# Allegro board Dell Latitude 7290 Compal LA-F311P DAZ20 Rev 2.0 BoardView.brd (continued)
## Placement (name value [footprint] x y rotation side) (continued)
PR1258  0_0402_5%  [R_0402]  45.6 52.84 0 bottom
PR1259  100K_0402_5%  [R_0402]  41.54 52.84 0 bottom
PR1260  0_0402_5%  [R_0402]  40.71 51.13 0 top
PR1261  0_0402_5%  [R_0402]  42.95 51.46 270 top
PR1262  100K_0402_1%  [R_0402]  46.33 108.98 180 top
PRP1  100_0804_8P4R_5%  [RP_0804_8P4R]  167.81 61.67 45 top
PT1  PAD~D  [TPC12]  32.51 58.58 0 top
PU1  MC74VHC1G08DFT2G SC70 5P AND  [TC7SH08FU_SSOP5]  56.85 121.18 270 bottom
PU2  AP2204R-3.3TRG1 SOT-89 3P LDO  [AP2204R-5P0TRG1_SOT89-3]  68.22 121.02 270 bottom
PU100  -  [SY8288BRAC_QFN20_3X3]  155.36 73.9 90 bottom
PU102  SYV828CRAC QFN 20P PWM  [SY8288CRAC_QFN20_3X3]  185.84 54.09 90 bottom
PU200  -  [SY8210AQVC_QFN19_4X3]  69.06 72.01 180 bottom
PU301  SY8286RAC_QFN20_3X3  [SY8288RAC_QFN20_3X3]  157.04 86.35 270 top
PU401  TPS62134CRGT_QFN16_3X3  [SY8057QDC_QFN16_3X3]  140.08 129.05 0 bottom
PU402  TPS62134DRGT_QFN16_3X3  [SY8057QDC_QFN16_3X3]  155.95 127.53 0 bottom
PU501  -  [RT8097ALGE_SOT23-6]  174.39 65.56 225 bottom
PU503  AP7361C-FGE-7-01 U-DFN3030 8P LDO  [AP7361C-FGE-7_U-DFN3030-8_3X3]  148.3 60.61 270 top
PU602  ISL95857AHRTZ-T TQFN 40P PWM  [ISL62883CHRTZ-T_TQFN40_5X5-S]  46.33 91.69 0 top
PU610  FDMF3035_PQFN31_5X5  [NCP302045MNTWG_PQFN33_5X5]  59.64 106.09 180 bottom
PU612  FDMF3035_PQFN31_5X5  [NCP302045MNTWG_PQFN33_5X5]  59.69 86.7 180 bottom
PU613  FDMF3035_PQFN31_5X5  [NCP302045MNTWG_PQFN33_5X5]  56.49 95.82 90 bottom
PU614  S IC ISL95808HRZ-TS2778 DFN MOSFET DRIVE  [ISL95808HRZ-TS2378_DFN8_2X2-S]  60.01 113.56 90 bottom
PU901  S IC ISL9538HRTZ-REV.C-T TQFN32P CHARGER  [ISL88738HRTZ-T_TQFN32_4X4]  58.57 55.64 180 top
PU903  MC74VHC1G08DFT2G SC70 5P AND  [TC7SH08FU_SSOP5]  46.25 55.4 270 bottom
PU1200  MC74VHC1G08DFT2G SC70 5P AND  [TC7SH08FU_SSOP5]  37.51 62.6 270 bottom
PU1201  -  [LM393DGKR_VSSOP8]  41.44 56.04 180 bottom
QC2  -  [DMN65D8LDW-7_SOT363-6]  150.96 109.75 270 bottom
QC6  -  [L2N7002WT1G_SC-70-3]  142.53 75.88 90 top
QC7  -  [LP2301ALT1G_SOT23-3]  149.27 83.49 270 bottom
QE2  -  [DMN65D8LDW-7_SOT363-6]  238.86 83.83 180 bottom
QE3  LMBT3904WT1G SC70-3  [MMBT3904WT1G_SC70-3]  117.93 101.69 90 top
QE4  LMBT3904WT1G SC70-3  [MMBT3904WT1G_SC70-3]  265.9 101.86 90 top
QE5  LMBT3904WT1G SC70-3  [MMBT3904WT1G_SC70-3]  235.99 79.39 90 top
QE6  LMBT3904WT1G SC70-3  [MMBT3904WT1G_SC70-3]  66.53 83.82 90 bottom
QE7  LMBT3904WT1G SC70-3  [MMBT3904WT1G_SC70-3]  149.57 59.52 0 bottom
QE11  -  [L2N7002WT1G_SC-70-3]  258.92 102.69 90 top
QE12  -  [L2N7002WT1G_SC-70-3]  245.9 102.81 0 top
QE15  -  [LP2301ALT1G_SOT23-3]  241.33 97.04 270 top
QE17  -  [L2N7002WT1G_SC-70-3]  233.13 97.11 0 top
QL1  -  [DMN65D8LDW-7_SOT363-6]  257.79 131.2 180 bottom
QL2  -  [DMN65D8LDW-7_SOT363-6]  260.64 131.2 180 bottom
QR1  -  [L2N7002WT1G_SC-70-3]  279.87 58.56 90 top
QT1  -  [DMN66D0LDW-7_SOT363-6]  39.96 80.26 90 top
QV1  -  [AO6405_TSOP6]  46.25 125.07 180 top
QV2  -  [L2N7002WT1G_SC-70-3]  40.47 123.13 0 top
QV3  -  [DMN65D8LDW-7_SOT363-6]  17.57 88.22 0 top
QV4  -  [L2N7002WT1G_SC-70-3]  22.19 75.19 0 top
QV5  -  [L2N7002WT1G_SC-70-3]  12.66 95.26 180 top
QV7  -  [L2N7002WT1G_SC-70-3]  48.6 122.17 0 top
QV8  -  [LP2301ALT1G_SOT23-3]  49.17 126.15 180 top
QZ1  -  [LP2301ALT1G_SOT23-3]  57.16 125.79 180 top
QZ2  -  [DMN65D8LDW-7_SOT363-6]  270.98 84.54 270 top
QZ3  DDTA144VCA-7-F_SOT23-3  [DDTA114EUA-7-F_SOT323-3]  285.84 11.35 0 bottom
QZ4  -  [L2N7002WT1G_SC-70-3]  241.5 120.81 270 bottom
QZ7  -  [DMN65D8LDW-7_SOT363-6]  268.56 82.23 90 top
QZ15  S TR BSS138W 1N SOT-323-3  [L2N7002WT1G_SC-70-3]  248.28 121.16 0 bottom
RA3  0_0603_5%  [R0603_0OHM]  263.29 55.76 0 top
RA5  2.2K_0402_5%  [R_0402]  250.9 61.86 0 top
RA6  2.2K_0402_5%  [R_0402]  250.9 60.97 0 top
RA7  16.2_0402_1%  [R_0402]  258.34 55.01 270 top
RA8  16.2_0402_1%  [R_0402]  259.23 55.01 270 top
RA9  33_0402_5%  [R_0402]  256.56 66.38 270 top
RA12  1K_0402_5%  [R_0402]  252.3 66.46 0 top
RA13  1K_0402_5%  [R_0402]  251.43 66.46 180 top
RA14  22_0402_5%  [R_0402]  258.6 66.38 270 top
RA17  33_0402_5%  [R_0402]  257.71 65.47 90 top
RA18  10K_0402_5%  [R_0402]  262.99 67.45 180 top
RA35  0_0402_5%  [R0402_0OHM]  251.37 53.03 180 top
RA36  0_0402_5%  [R0402_0OHM]  251.37 52.14 180 top
RA37  0_0402_5%  [R0402_0OHM]  250.1 59.95 180 top
RA38  0_0402_5%  [R0402_0OHM]  281.75 46.79 90 top
RA39  0_0402_5%  [R0402_0OHM]  282.45 31.54 225 top
RA44  100K_0402_5%  [R_0402]  254.47 55.01 270 top
RA45  10K_0402_5%  [R_0402]  251.43 65.57 180 top
RA48  0_0402_5%  [R0402_0OHM]  261.77 69.49 270 top
RA50  0_0402_5%  [R_0402]  260.88 69.49 270 top
RA51  10K_0402_5%  [R_0402]  252.3 65.57 0 top
RA52  100K_0402_5%  [R_0402]  259.55 66.38 270 top
RA53  0_0402_5%  [R_0402]  250.1 58.18 180 top
RA54  0_0402_5%  [R0402_0OHM]  250.1 59.07 180 top
RA55  0_0402_5%  [R0402_0OHM]  281.32 36.9 0 top
RA56  0_0402_5%  [R0402_0OHM]  281.32 35.7 0 top
RA57  4.7K_0402_5%  [R_0402]  257.45 55.01 270 top
RA58  4.7K_0402_5%  [R_0402]  256.56 55.01 270 top
RA59  100K_0402_1%  [R_0402]  251.98 69.16 0 top
RA60  200K_0402_1%  [R_0402]  253.76 69.16 0 top
RA61  100K_0402_5%  [R_0402]  252.12 68.22 270 top
RC1  100K_0402_5%  [R_0402]  129.92 106.92 0 top
RC2  24.9_0402_1%  [R_0402]  102.75 109.98 270 top
RC3  100_0402_1%  [R_0402]  125.32 120.53 180 top
RC4  200_0402_1%  [R_0402]  137.17 96.21 0 bottom
RC5  121_0402_1%  [R_0402]  120.74 84.48 270 top
RC6  80.6_0402_1%  [R_0402]  122.01 84.48 270 top
RC7  100_0402_1%  [R_0402]  122.9 84.48 270 top
RC10  1K_0402_1%  [R_0402]  148.99 100.35 270 top
RC11  1K_0402_1%  [R_0402]  148.93 91.75 0 bottom
RC12  1K_0402_5%  [R_0402]  134.52 104.84 90 top
RC14  1K_0402_5%  [R_0402]  135.41 104.84 270 top
RC15  1K_0402_5%  [R_0402]  142.19 105.93 0 bottom
RC16  15_0402_5%  [R_0402]  148.92 90.75 0 bottom
RC17  1K_0402_5%  [R_0402]  142.19 106.7 0 bottom
RC19  499_0402_1%  [R_0402]  142.57 102.37 0 bottom
RC20  499_0402_1%  [R_0402]  142.19 103.26 0 bottom
RC21  8.2K_0402_1%  [R_0402]  144.53 84.72 0 top
RC22  22_0402_5%  [R_0402]  137.5 84.48 270 top
RC23  2.2K_0402_5%  [R_0402]  132.35 105.67 0 top
RC25  4.7K_0402_5%  [R_0402]  142.19 105.04 0 bottom
RC27  8.2K_0402_5%  [R_0402]  136.61 84.48 270 top
RC28  33_0402_5%  [R_0402]  157.28 102.21 180 top
RC29  33_0402_5%  [R_0402]  156.97 93.45 270 top
RC30  1K_0402_5%  [R_0402]  160.49 96.42 270 top
RC31  1K_0402_5%  [R_0402]  160.49 93.6 90 top
RC32  0_0402_5%  [R_0402]  163.74 102.5 180 bottom
RC33  0_0402_5%  [R0402_0OHM]  162.83 100.47 0 bottom
RC34  0_0402_5%  [R0402_0OHM]  162.83 99.39 0 bottom
RC35  0_0402_5%  [R0402_0OHM]  163.74 97.93 180 bottom
RC36  0_0402_5%  [R0402_0OHM]  163.74 95.83 180 bottom
RC37  0_0402_5%  [R0402_0OHM]  163.74 96.72 180 bottom
RC38  0_0402_5%  [R0402_0OHM]  163.66 93.91 90 bottom
RC39  33_0402_5%  [R_0402]  161.38 96.42 270 top
RC40  0_0402_5%  [R0402_0OHM]  163.66 92.07 90 bottom
RC41  0_0402_5%  [R0402_0OHM]  149.95 101.22 90 top
RC42  0_0402_5%  [R_0402]  163.74 101.61 180 bottom
RC43  33_0402_5%  [R_0402]  161.39 97.29 180 top
RC44  113_0402_1%  [R_0402]  130.99 102.58 90 top
RC45  100_0402_1%  [R_0402]  129.96 109.58 0 top
RC46  1M_0402_1%  [R_0402]  114.32 118.12 0 bottom
RC47  10K_0402_5%  [R_0402]  144.75 96.61 180 bottom
RC48  1K_0402_5%  [R_0402]  124.31 82.69 180 top
RC50  10K_0402_5%  [R_0402]  144.76 95.84 180 bottom
RC51  10K_0402_5%  [R_0402]  144.75 98.31 180 bottom
RC52  2.7K_0402_1%  [R_0402]  119.3 104.96 90 top
RC54  10M_0402_5%  [R_0402]  133.87 82.62 0 top
RC56  20K_0402_5%  [R_0402]  130.77 82.26 270 top
RC57  20K_0402_5%  [R_0402]  128.93 80.66 0 top
RC59  10K_0402_5%  [R_0402]  138.82 83.58 0 top
RC60  0_0402_5%  [R_0402]  157.94 118.57 0 bottom
RC62  0_0402_5%  [R0402_0OHM]  157.94 119.45 0 bottom
RC65  100K_0402_5%  [R_0402]  155.33 117.42 0 bottom
RC67  1K_0402_5%  [R_0402]  136.61 79.44 90 top
RC68  10K_0402_5%  [R_0402]  141.62 81.29 0 top
RC69  1M_0402_5%  [R_0402]  127.42 83.58 180 top
RC71  1K_0402_5%  [R_0402]  90.89 120.65 90 bottom
RC72  8.2K_0402_5%  [R_0402]  131.02 84.48 270 top
RC73  10K_0402_5%  [R_0402]  141.57 84.86 270 top
RC74  10K_0402_5%  [R_0402]  143.35 84.56 270 top
RC75  10K_0402_5%  [R_0402]  126.71 81.43 270 top
RC77  1K_0402_5%  [R_0402]  84.78 121.17 0 bottom
RC78  60.4_0402_1%  [R_0402]  90.89 119.78 270 bottom
RC79  49.9_0402_1%  [R_0402]  96.29 119.76 90 bottom
RC80  1K_0402_5%  [R_0402]  95.41 120.66 180 bottom
RC81  51_0402_5%  [R_0402]  99.02 121.09 90 bottom
RC82  100_0402_5%  [R_0402]  99.91 121.09 90 bottom
RC83  1K_0402_5%  [R_0402]  89.11 120.65 90 bottom
RC84  499_0402_1%  [R_0402]  88.23 119.78 270 bottom
RC86  51_0402_5%  [R_0402]  99.83 120.53 0 top
RC87  1K_0402_5%  [R_0402]  98.07 119.76 90 bottom
RC88  49.9_0402_1%  [R_0402]  123.79 84.48 270 top
RC89  49.9_0402_1%  [R_0402]  125.12 84.48 270 top
RC90  49.9_0402_1%  [R_0402]  92.71 109.36 180 top
RC91  49.9_0402_1%  [R_0402]  92.71 108.47 180 top
RC92  33_0402_5%  [R_0402]  119.98 79.87 90 top
RC93  33_0402_5%  [R_0402]  119.09 79.87 90 top
RC94  33_0402_5%  [R_0402]  124.13 77.63 180 top
RC95  33_0402_5%  [R_0402]  122.32 76.78 90 top
RC96  200_0402_1%  [R_0402]  129.31 103.47 0 top
RC109  1K_0402_5%  [R_0402]  84.48 118.87 90 bottom
RC110  10K_0402_1%  [R_0402]  87.21 118.87 90 bottom
RC112  10K_0402_1%  [R_0402]  86.32 118.87 90 bottom
RC113  10K_0402_1%  [R_0402]  87.48 120.66 180 bottom
RC114  49.9_0402_1%  [R_0402]  97.69 110.09 180 top
RC115  1.5K_0402_5%  [R_0402]  89.04 133.17 0 top
RC120  100K_0402_5%  [R_0402]  91.78 118.87 90 bottom
RC121  0_0402_5%  [R_0402]  99.02 127.13 90 bottom
RC122  0_0402_5%  [R_0402]  98.13 127.13 90 bottom
RC123  1K_0402_5%  [R_0402]  90 120.65 90 bottom
RC124  1K_0402_5%  [R_0402]  124.93 81.43 270 top
RC126  1K_0402_5%  [R_0402]  90.26 126.24 90 bottom
RC128  0_0402_5%  [R_0402]  88.48 126.24 90 bottom
RC129  0_0402_5%  [R_0402]  89.37 126.24 90 bottom
RC130  51_0402_5%  [R_0402]  101.62 120.52 90 top
RC131  51_0402_5%  [R_0402]  78.41 121.9 270 bottom
RC132  150_0402_5%  [R_0402]  92.04 127.15 270 bottom
RC133  1.5K_0402_5%  [R_0402]  148.99 101.22 90 top
RC134  51_0402_5%  [R_0402]  79.78 119.78 270 bottom
RC135  100_0402_5%  [R_0402]  82 119.78 270 bottom
RC136  51_0402_5%  [R_0402]  82.46 125.16 0 bottom
RC137  3K_0402_5%  [R_0402]  88.17 133.17 180 top
RC138  51_0402_5%  [R_0402]  102.89 127.98 270 bottom
RC139  51_0402_5%  [R_0402]  86.69 128.03 0 bottom
RC140  100_0402_1%  [R_0402]  110.08 120.53 180 top
RC141  100_0402_1%  [R_0402]  110.95 120.53 0 top
RC143  0_0603_5%  [R0603_0OHM]  118.64 108.72 180 top
RC152  56_0402_1%  [R_0402]  93.57 120.66 180 bottom
RC153  220_0402_5%  [R_0402]  93.56 118.87 90 bottom
RC157  100_0402_1%  [R_0402]  92.67 118.87 90 bottom
RC161  100_0402_1%  [R_0402]  88.47 107.39 0 top
RC163  100_0402_1%  [R_0402]  88.47 108.28 0 top
RC165  100_0402_1%  [R_0402]  117.64 96.89 135 top
RC166  100_0402_1%  [R_0402]  117.75 120.46 90 top
RC167  100_0402_1%  [R_0402]  118.76 97.22 135 top
RC168  100_0402_1%  [R_0402]  116.86 121.37 270 top
RC169  0_0603_5%  [R0603_0OHM]  129.31 126.57 270 bottom
RC170  0_0402_5%  [R0402_0OHM]  124.99 127.95 270 bottom
RC171  0_0402_5%  [R0402_0OHM]  125.88 127.95 270 bottom
RC173  0_0402_5%  [R0402_0OHM]  122.33 127.95 270 bottom
RC175  2.2K_0402_5%  [R_0402]  132.03 109.94 0 top
RC176  2.2K_0402_5%  [R_0402]  148.99 113.31 270 top
RC177  2.2K_0402_5%  [R_0402]  148.99 114.17 90 top
RC178  2.2K_0402_5%  [R_0402]  132.03 109.05 0 top
RC183  8.2K_0402_5%  [R_0402]  140.68 84.86 270 top
RC184  8.2K_0402_5%  [R_0402]  140.1 97.98 90 top
RC186  4.7K_0402_5%  [R_0402]  134.83 84.48 270 top
RC187  4.7K_0402_5%  [R_0402]  123.21 79.36 0 top
RC189  10K_0402_5%  [R_0402]  144.75 97.42 180 bottom
RC190  10K_0402_5%  [R_0402]  138.82 82.69 0 top
RC211  0_0402_5%  [R_0402]  145.05 81.54 0 top
RC212  0_0402_5%  [R0402_0OHM]  148.11 85.62 270 top
RC214  0_0402_5%  [R_0402]  147.9 80.02 270 top
RC215  0_0402_5%  [R_0402]  125.82 80.52 90 top
RC216  0_0603_5%  [R0603_0OHM]  93.37 133.55 180 top
RC217  0_0402_5%  [R_0402]  91.15 126.24 90 bottom
RC218  150_0402_5%  [R_0402]  92.04 125.37 270 bottom
RC219  10K_0402_5%  [R_0402]  91.15 125.37 270 bottom
RC220  100K_0402_1%  [R_0402]  125.8 78.75 0 top
RC221  0_0402_5%  [R0402_0OHM]  230.69 87.77 335 bottom
RC222  1K_0402_5%  [R_0402]  226.85 80.98 225 bottom
RC223  1K_0402_5%  [R_0402]  124.13 78.5 180 top
RC224  1K_0402_5%  [R_0402]  149.83 114.31 180 bottom
RC225  8.2K_0402_5%  [R_0402]  149.64 117.74 180 bottom
RC227  8.2K_0402_5%  [R_0402]  150.51 117.74 0 bottom
RC228  0_0402_5%  [R0402_0OHM]  77.46 121.9 270 bottom
RC229  0_0402_5%  [R0402_0OHM]  80.67 119.78 270 bottom
RC230  0_0402_5%  [R0402_0OHM]  82.89 119.78 270 bottom
RC231  0_0402_5%  [R0402_0OHM]  109.55 97.52 0 top
RC234  0_0402_5%  [R_0402]  139.67 100.85 180 top
RC235  0_0402_5%  [R0402_0OHM]  137.88 99.95 90 top
RC237  10K_0402_5%  [R_0402]  140.1 96.71 90 bottom
RC239  0_0402_5%  [R_0402]  97.24 127.13 90 bottom
RC240  0_0402_5%  [R_0402]  96.35 127.13 90 bottom
RC241  1.5K_0402_5%  [R_0402]  91.35 127.2 180 top
RC243  10K_0402_5%  [R_0402]  137.5 79.44 90 top
RC244  0_0402_5%  [R0402_0OHM]  157.94 120.34 0 bottom
RC267  10K_0402_5%  [R_0402]  138.31 97.61 0 bottom
RC268  10K_0402_5%  [R_0402]  137.25 97.22 90 bottom
RC272  10K_0402_5%  [R_0402]  128.54 117.72 0 bottom
RC278  10K_0402_5%  [R_0402]  141.9 98.94 180 bottom
RC279  10K_0402_5%  [R_0402]  147.22 106.11 90 bottom
RC282  100K_0402_5%  [R_0402]  144.98 85.61 0 top
RC283  10K_0402_5%  [R_0402]  145.64 101.48 180 bottom
RC287  100K_0402_5%  [R_0402]  134.36 102.96 0 top
RC288  10K_0402_5%  [R_0402]  135.91 121.12 90 bottom
RC290  0_0402_5%  [R0402_0OHM]  151.81 114.31 180 bottom
RC291  10K_0402_5%  [R_0402]  147.98 115.95 90 bottom
RC292  10K_0402_5%  [R_0402]  139.08 98.94 0 bottom
RC296  0_0402_5%  [R0402_0OHM]  132.94 82.62 180 top
RC297  0_0402_5%  [R_0402]  104.93 120.52 90 top
RC298  0_0402_5%  [R_0402]  103.78 120.52 90 top
RC299  0_0603_5%  [R0603_0OHM]  140.8 121.23 270 top
RC300  0_0402_5%  [R0402_0OHM]  127.66 122.52 270 bottom
RC301  0_0402_5%  [R0402_0OHM]  149.71 106.56 180 bottom
RC302  0_0402_5%  [R0402_0OHM]  125.82 123.63 270 top
RC303  0_0402_5%  [R0402_0OHM]  124.93 123.63 270 top
RC304  0_0402_5%  [R0402_0OHM]  131.55 100.98 180 top
RC305  0_0402_5%  [R0402_0OHM]  130.64 98.49 90 top
RC306  0_0402_5%  [R0402_0OHM]  135.22 99.38 90 top
RC307  0_0402_5%  [R0402_0OHM]  134.33 99.38 90 top
RC308  0_0402_5%  [R0402_0OHM]  136.42 103.06 90 top
RC309  0_0603_5%  [R0603_0OHM]  136.04 121.99 270 top
RC310  0_0603_5%  [R0603_0OHM]  129.44 123.77 270 top
RC311  10K_0402_5%  [R_0402]  128.93 84.48 270 top
RC313  0_0402_5%  [R_0402]  139.04 101.8 180 bottom
RC316  1K_0402_5%  [R_0402]  160.49 92.73 270 top
RC317  150K_0402_5%  [R_0402]  139.22 97.98 90 top
RC318  2.2K_0402_5%  [R_0402]  148.12 107.96 180 bottom
RC319  2.2K_0402_5%  [R_0402]  149.86 111.06 180 bottom
RC323  10K_0402_5%  [R_0402]  146.89 102.37 0 bottom
RC324  59_0402_1%  [R_0402]  108.29 110.07 270 top
RC325  0_0402_5%  [R0402_0OHM]  157.94 117.68 0 bottom
RC328  0_0402_5%  [R0402_0OHM]  96.59 118.88 0 bottom
RC330  49.9K_0402_1%  [R_0402]  146 100.21 0 bottom
RC331  49.9K_0402_1%  [R_0402]  146 99.32 0 bottom
RC337  0_0402_5%  [R0402_0OHM]  137.88 111.57 90 bottom
RC338  1K_0402_5%  [R_0402]  136.99 111.57 90 bottom
RC344  10K_0402_5%  [R_0402]  141.57 82.17 90 top
RC345  100K_0402_5%  [R_0402]  135.61 108.28 180 bottom
RC346  10K_0402_5%  [R_0402]  136.8 121.12 90 bottom
RC347  499_0402_1%  [R_0402]  142.57 101.48 0 bottom
RC348  499_0402_1%  [R_0402]  142.19 104.15 0 bottom
RC349  100_0402_1%  [R_0402]  137.95 82.7 270 top
RC362  1K_0402_5%  [R_0402]  141.9 97.17 180 bottom
RC363  1K_0402_5%  [R_0402]  141.9 98.05 180 bottom
RC366  15_0402_5%  [R_0402]  148.92 85.9 0 bottom
RC367  15_0402_5%  [R_0402]  148.92 87.68 0 bottom
RC368  15_0402_5%  [R_0402]  148.92 86.79 0 bottom
RC369  15_0402_5%  [R_0402]  148.92 88.57 0 bottom
RC371  10K_0402_5%  [R_0402]  140.12 107.39 180 bottom
RC372  10K_0402_5%  [R_0402]  140.12 108.28 180 bottom
RC373  0_0402_5%  [R0402_0OHM]  146.91 97.42 180 bottom
RC374  0_0402_5%  [R0402_0OHM]  146.91 96.53 180 bottom
RC376  0_0402_5%  [R0402_0OHM]  139.74 84.47 180 top
RC377  0_0402_5%  [R0402_0OHM]  146.91 98.31 180 bottom
RC378  0_0402_5%  [R0402_0OHM]  139.74 81.8 180 top
RC387  10K_0402_5%  [R_0402]  142.45 84.86 270 top
RC400  10K_0402_5%  [R_0402]  136.66 107.39 0 bottom
RC401  10K_0402_5%  [R_0402]  136.66 108.28 0 bottom
RC402  49.9K_0402_1%  [R_0402]  143.27 100.28 0 bottom
RC403  49.9K_0402_1%  [R_0402]  143.27 99.39 0 bottom
RC405  100K_0402_5%  [R_0402]  137.25 101.34 90 bottom
RC407  33_0402_5%  [R_0402]  155.85 97.92 90 top
RC408  33_0402_5%  [R_0402]  156.74 97.92 90 top
RC409  33_0402_5%  [R_0402]  157.63 97.92 90 top
RC410  33_0402_5%  [R_0402]  158.65 97.92 90 top
RC411  10K_0402_5%  [R_0402]  122.82 81.8 0 top
RC412  10K_0402_5%  [R_0402]  146.09 107.96 180 bottom
RC413  10K_0402_5%  [R_0402]  133.63 103.84 0 top
RC414  10K_0402_5%  [R_0402]  135.72 84.48 270 top
RC415  1M_0402_1%  [R_0402]  130.76 118.76 0 bottom
RC417  0_0402_5%  [R_0402]  133.83 118.76 180 bottom
RC418  0_0402_5%  [R_0402]  131.67 117.87 180 bottom
RC419  0_0402_5%  [R_0402]  114.32 117.23 0 bottom
RC420  0_0402_5%  [R_0402]  112.55 118.12 0 bottom
RC431  100K_0402_5%  [R_0402]  148.34 76.91 0 top
RC432  499K_0402_1%  [R_0402]  145.5 83.53 270 bottom
RC433  49.9K_0402_1%  [R_0402]  142.43 77.58 0 top
RC436  0_0402_5%  [R_0402]  101.82 127.82 270 top
RC437  0_0402_5%  [R_0402]  104.06 108.85 270 top
RC438  0_0402_5%  [R_0402]  102.16 97.51 270 top
RC439  0_0402_5%  [R0402_0OHM]  151.03 82.96 90 bottom
RC440  0_0402_5%  [R_0402]  147.91 81 90 top
RC441  0_0402_5%  [R0402_0OHM]  155.22 124.6 270 top
RC442  0_0402_5%  [R_0402]  155.22 121.8 90 top
RC443  0_0402_5%  [R_0402]  147.23 87.21 270 top
RC444  0_0402_5%  [R0402_0OHM]  144.37 82.92 90 top
RC445  0_0402_5%  [R_0402]  152.95 124.31 0 top
RC550  1K_0402_5%  [R_0402]  147.19 84.71 180 top
RC553  10K_0402_5%  [R_0402]  145.38 104.38 180 bottom
RC554  10K_0402_5%  [R_0402]  146.11 104.39 0 bottom
RC555  10K_0402_5%  [R_0402]  142.17 107.49 0 bottom
RC556  10K_0402_5%  [R_0402]  142.17 108.27 0 bottom
RC560  0_0402_5%  [R_0402]  139.55 95.26 180 bottom
RC561  0_0402_5%  [R_0402]  149.57 103.78 225 bottom
RD4  0_0402_5%  [R_0402]  145.52 56.59 180 top
RD5  0_0402_5%  [R0402_0OHM]  143.36 56.59 180 top
RD6  0_0402_5%  [R_0402]  145.52 55.7 180 top
RD7  0_0402_5%  [R0402_0OHM]  143.36 55.7 180 top
RD8  0_0402_5%  [R_0402]  123.23 51.83 180 top
RD9  0_0402_5%  [R0402_0OHM]  122.31 52.72 0 top
RD10  0_0603_5%  [R0603_0OHM]  146.58 56.46 90 top
RD11  470_0402_1%  [R_0402]  103.58 53.48 0 top
RD12  0_0402_5%  [R0402_0OHM]  103.58 52.59 0 top
RD14  1K_0402_5%  [R_0402]  109.76 53.22 180 top
RD15  1K_0402_1%  [R_0402]  116.98 54.18 0 top
RD16  1K_0402_1%  [R_0402]  118.76 52.4 0 top
RD17  2_0402_1%  [R_0402]  117.88 53.3 270 top
RD18  24.9_0402_1%  [R_0402]  116.1 53.3 270 top
RD19  100K_0402_5%  [R_0402]  76.13 77.28 0 top
RE5  10K_0402_5%  [R_0402]  248.12 97.22 90 top
RE8  100K_0402_5%  [R_0402]  256.63 96.07 90 top
RE10  100K_0402_5%  [R_0402]  245.25 99.14 270 top
RE11  100K_0402_5%  [R_0402]  247.04 80.92 270 top
RE12  100K_0402_5%  [R_0402]  259.92 79.96 0 top
RE20  100K_0402_5%  [R_0402]  258.01 81.51 270 top
RE21  10K_0402_5%  [R_0402]  246.59 96.2 90 top
RE25  100K_0402_5%  [R_0402]  259.28 96.98 0 top
RE26  10_0402_5%  [R_0402]  261.97 96.98 180 top
RE30  0_0402_5%  [R0402_0OHM]  288.36 121.36 0 bottom
RE31  100K_0402_5%  [R_0402]  244.24 78.64 270 top
RE32  0_0402_5%  [R0402_0OHM]  244.24 79.55 90 top
RE33  1K_0402_5%  [R_0402]  243.36 77.72 90 top
RE35  10K_0402_5%  [R_0402]  258.41 96.07 90 top
RE37  2.2K_0402_5%  [R_0402]  260.82 82.32 270 top
RE38  10K_0402_5%  [R_0402]  257.52 96.07 90 top
RE43  2.2K_0402_5%  [R_0402]  259.55 81.88 270 top
RE48  10K_0402_5%  [R_0402]  237.46 128.69 270 bottom
RE51  10K_0402_5%  [R_0402]  238.35 128.69 270 bottom
RE55  100K_0402_5%  [R_0402]  246.09 80.92 270 top
RE56  10K_0402_5%  [R_0402]  236.12 84.29 90 top
RE57  1K_0402_5%  [R_0402]  245.34 75.78 270 top
RE58  100K_0402_5%  [R_0402]  246.09 77.72 90 top
RE59  0_0402_5%  [R0402_0OHM]  255.04 97.22 90 top
RE60  43_0402_5%  [R_0402]  253.64 95.76 90 top
RE63  100K_0402_5%  [R_0402]  250.02 99.75 0 top
RE64  300_0402_5%  [R_0402]  256.12 79.91 270 top
RE65  100_0402_1%  [R_0402]  249.07 101.79 180 top
RE67  10K_0402_5%  [R_0402]  236.02 83.7 90 bottom
RE68  100K_0402_5%  [R_0402]  239.32 85.33 0 top
RE69  8.2K_0402_5%  [R_0402]  267.94 100.98 180 top
RE70  2.2K_0402_5%  [R_0402]  261.95 102.56 0 top
RE71  10_0402_1%  [R_0402]  288.24 127.07 0 bottom
RE72  10K_0402_5%  [R_0402]  286.21 121.36 0 bottom
RE73  10K_0402_5%  [R_0402]  286.21 122.31 0 bottom
RE74  10K_0402_5%  [R_0402]  288.36 120.47 0 bottom
RE75  100K_0402_5%  [R_0402]  286.21 123.26 0 bottom
RE77  1.58K_0402_1%  [R_0402]  244.45 94.5 180 top
RE79  4.3K_0402_5%  [R_0402]  251.15 102.81 180 top
RE83  100K_0402_5%  [R_0402]  250.85 97.92 90 top
RE84  100K_0402_5%  [R_0402]  250.9 101.94 180 top
RE85  100K_0402_5%  [R_0402]  250.93 100.62 180 top
RE86  10K_0402_5%  [R_0402]  288.36 123.26 0 bottom
RE90  0_0402_5%  [R0402_0OHM]  262.86 103.45 180 top
RE91  100K_0402_5%  [R_0402]  249.96 97.92 90 top
RE92  100K_0402_5%  [R_0402]  250.65 74.62 0 top
RE93  100K_0201_5%  [R_0201]  245.16 99.98 0 top
RE94  75_0402_5%  [R_0402]  247.08 103.97 0 top
RE95  100K_0402_5%  [R_0402]  260.79 92.12 0 top
RE274  0_0402_5%  [R_0402]  259.93 78.17 90 top
RE275  0_0402_5%  [R0402_0OHM]  260.82 79.08 270 top
RE280  0_0402_5%  [R_0402]  262.16 99.07 180 top
RE288  100_0402_5%  [R_0402]  252.25 95.76 90 top
RE290  0_0402_5%  [R0402_0OHM]  244.5 84.86 270 top
RE292  0_0402_5%  [R_0402]  261.25 98.18 0 top
RE300  130K_0402_5%  [R_0402]  256.82 98.77 270 top
RE301  10K_0402_5%  [R_0402]  247.36 96.2 90 top
RE302  2.2K_0402_5%  [R_0402]  241.15 87.13 180 top
RE303  2.2K_0402_5%  [R_0402]  241.15 86.24 180 top
RE304  0_0402_5%  [R_0402]  267 100.02 180 top
RE306  0_0402_5%  [R_0402]  289.28 122.31 180 bottom
RE308  0_0402_5%  [R_0402]  257.58 101.05 270 top
RE312  300_0402_5%  [R_0402]  257.26 77.62 270 top
RE313  10K_0402_5%  [R_0402]  257.02 78.62 0 top
RE314  100_0402_1%  [R_0402]  251.09 79.13 0 top
RE318  0_0402_5%  [R0402_0OHM]  249.52 75.78 270 top
RE324  100K_0402_5%  [R_0402]  246.21 75.78 270 top
RE340  10K_0402_5%  [R_0402]  270.28 80.26 90 top
RE342  10K_0402_5%  [R_0402]  262.14 84.12 0 top
RE343  130K_0402_5%  [R_0402]  249.72 77.73 180 top
RE349  43K_0402_1%  [R_0402]  263.05 83.2 180 top
RE350  33_0402_5%  [R_0402]  247.99 75.78 270 top
RE362  100K_0402_5%  [R_0402]  247.93 77.79 90 top
RE365  100K_0402_5%  [R_0402]  208.19 58.49 180 top
RE375  0_0402_5%  [R_0402]  248.87 55.07 0 bottom
RE505  100K_0402_5%  [R_0402]  254.23 127.58 180 bottom
RE506  0_0402_5%  [R0402_0OHM]  259.37 90.71 90 top
RE507  100K_0402_5%  [R_0402]  237.97 83.48 90 top
RE508  100K_0402_5%  [R_0402]  237.97 86.17 270 top
RE526  10K_0402_5%  [R_0402]  221.33 55.19 180 top
RE532  4.7K_0402_5%  [R_0402]  229.94 61.35 0 bottom
RE536  0_0402_5%  [R0402_0OHM]  245.07 97.14 270 top
RE539  100_0402_5%  [R_0402]  245.22 81.08 270 top
RE541  100K_0402_5%  [R_0402]  241.43 99.46 0 top
RE543  1M_0402_5%  [R_0402]  237.77 99.2 0 top
RE546  10K_0402_5%  [R_0402]  238.69 103.2 0 top
RE547  100K_0402_5%  [R_0402]  264.06 88.91 0 top
RE548  0_0402_5%  [R0402_0OHM]  235.23 84.29 90 top
RE549  100K_0402_5%  [R_0402]  255.8 76.77 90 top
RE550  100K_0402_5%  [R_0402]  258.22 76.12 90 top
RE551  0_0402_5%  [R_0402]  237.72 105.02 0 top
RE552  0_0402_5%  [R0402_0OHM]  253.36 104.09 0 top
RE560  0_0402_5%  [R_0402]  242 54.5 180 bottom
RE561  100K_0402_5%  [R_0402]  262.16 82.3 270 top
RE565  0_0402_5%  [R_0402]  245.83 96.23 90 top
RI13  10K_0402_5%  [R_0402]  275.3 78.74 90 top
RI14  22.1K_0402_1%  [R_0402]  280.58 76.53 180 top
RI27  0_0402_5%  [R_0402-NPM]  234.44 104.27 180 top
RI28  0_0402_5%  [R_0402-NPM]  234.44 105.16 180 top
RI29  0_0402_5%  [R_0402-NPM]  230.78 100.77 90 top
RI30  0_0402_5%  [R_0402-NPM]  229.89 100.77 90 top
RI47  0_0402_5%  [R_0402-NPM]  234.44 107.05 180 top
RI48  0_0402_5%  [R_0402-NPM]  234.44 106.16 180 top
RI49  0_0402_5%  [R_0402-NPM]  228.93 79.18 0 bottom
RI50  0_0402_5%  [R_0402-NPM]  228.93 78.29 0 bottom
RL1  10K_0402_5%  [R_0402]  245.34 131.27 180 bottom
RL2  10K_0402_5%  [R_0402]  243.22 130.25 0 bottom
RL3  0_0402_5%  [R0402_0OHM]  245.58 120.86 270 top
RL4  4.7K_0402_5%  [R_0402]  241.84 123.2 180 top
RL5  10K_0402_5%  [R_0402]  242.92 119.96 180 top
RL6  4.7K_0402_5%  [R_0402]  241.13 120.86 270 top
RL7  0_0402_5%  [R0402_0OHM]  242.01 119.07 0 top
RL8  0_0603_5%  [R0603_0OHM]  241.7 125.04 180 bottom
RL9  10K_0402_5%  [R_0402]  243.8 120.86 270 top
RL11  1M_0402_5%  [R_0402]  248.3 120.34 0 top
RL12  1K_0402_5%  [R_0402]  246.04 129.23 180 bottom
RL13  3.01K_0402_1%  [R_0402]  250.09 121.25 270 top
RL14  150_0402_5%  [R_0402]  282.41 121.05 270 top
RL15  75_0402_1%  [R_0402]  270.15 119.06 90 top
RL16  75_0402_1%  [R_0402]  268.88 119.06 90 top
RL17  75_0402_1%  [R_0402]  262.53 119.05 90 top
RL18  75_0402_1%  [R_0402]  261.26 119.05 90 top
RL19  150_0402_5%  [R_0402]  281.46 121.05 270 top
RL20  150_0402_5%  [R_0402]  280.5 121.05 270 top
RL29  1M_0402_5%  [R_0402]  255.23 132.21 90 top
RL30  1M_0402_5%  [R_0402]  256.12 132.21 90 top
RL34  0_0402_5%  [R0402_0OHM]  246.52 120.34 0 top
RL70  10K_0402_5%  [R_0402]  145.64 102.37 180 bottom
RL71  2.2_0603_5%  [R_0603]  252.18 121.99 0 top
RL72  2.2_0603_5%  [R_0603]  252.18 123.2 0 top
RL73  2.2_0603_5%  [R_0603]  252.18 124.41 0 top
RL74  2.2_0603_5%  [R_0603]  252.18 125.61 0 top
RL75  2.2_0603_5%  [R_0603]  251.93 126.82 0 top
RL76  2.2_0603_5%  [R_0603]  251.93 128.03 0 top
RL77  2.2_0603_5%  [R_0603]  251.8 129.23 0 top
RL78  2.2_0603_5%  [R_0603]  251.8 130.44 0 top
RN37  10K_0402_5%  [R_0402]  23.4 46.15 90 top
RN99  0_0402_5%  [R0402_0OHM]  12.98 47.38 90 bottom
RN100  0_0402_5%  [R_0402]  25.17 51.18 90 top
RPC1  33_0804_8P4R_5%  [RP_0804_8P4R]  158.14 95.86 270 top
RPC3  10K_8P4R_5%  [RP_0804_8P4R]  128.85 119.17 90 bottom
RPC4  10K_8P4R_5%  [RP_0804_8P4R]  146.39 109.24 0 bottom
RPE7  10K_8P4R_5%  [RP_0804_8P4R]  289.08 125.86 180 bottom
RPE9  100K_0804_8P4R_5%  [RP_0804_8P4R]  261.77 94.74 0 top
RPE10  100K_0804_8P4R_5%  [RP_0804_8P4R]  258.68 99.13 90 top
RPE11  100K_0804_8P4R_5%  [RP_0804_8P4R]  254.71 77.74 270 top
RPE12  2.2K_0804_8P4R_5%  [RP_0804_8P4R]  261.5 90.93 0 top
RR3  10K_0402_5%  [R_0402]  273.76 69.53 270 top
RR4  6.2K_0402_1%  [R_0402]  270.99 61.76 180 top
RR5  0_0402_5%  [R0402_0OHM]  278.61 62.41 270 top
RR6  0_0402_5%  [R0402_0OHM]  279.31 64.15 0 top
RR7  0_0402_5%  [R0402_0OHM]  279.32 65.02 0 top
RR8  0_0402_5%  [R0402_0OHM]  279.27 65.93 0 top
RR9  0_0402_5%  [R0402_0OHM]  276.82 61.17 270 top
RR10  0_0402_5%  [R0402_0OHM]  277.71 61.17 270 top
RR19  10K_0402_5%  [R_0402]  272.85 68.62 90 top
RR274  0_0603_5%  [R0603_0OHM]  274.72 72.65 270 top
RT1  3.3K_0402_5%  [R_0402]  40.48 80.34 0 bottom
RT2  2.2K_0402_5%  [R_0402]  37.82 89.16 180 top
RT3  2.2K_0402_5%  [R_0402]  37.82 88.15 180 top
RT4  3.3K_0402_5%  [R_0402]  37.82 87.13 180 top
RT5  10K_0402_5%  [R_0402]  32.02 103.45 0 top
RT6  10K_0402_5%  [R_0402]  31.26 105.23 0 top
RT7  10K_0402_5%  [R_0402]  31.26 104.34 0 top
RT8  10K_0402_5%  [R_0402]  32.02 102.56 0 top
RT9  0_0402_5%  [R0402_0OHM]  38.73 79.12 0 bottom
RT10  0_0402_5%  [R_0402]  40.02 77.23 90 bottom
RT11  10K_0402_5%  [R_0402]  24.03 105.42 90 top
RT12  2.2K_0402_5%  [R_0402]  31.22 108.15 90 top
RT13  2.2K_0402_5%  [R_0402]  33.89 108.15 90 top
RT14  2.2K_0402_5%  [R_0402]  38.71 112.15 180 top
RT15  2.2K_0402_5%  [R_0402]  37.49 108.55 270 top
RT16  10K_0402_5%  [R_0402]  28.85 108.3 90 top
RT17  10K_0402_5%  [R_0402]  24.68 108.19 90 bottom
RT18  2.2K_0402_5%  [R_0402]  28.6 108.21 90 bottom
RT19  2.2K_0402_5%  [R_0402]  29.49 108.21 90 bottom
RT20  10K_0402_5%  [R_0402]  26.78 108.18 90 bottom
RT21  1M_0402_5%  [R_0402]  19.8 101.57 180 bottom
RT22  1M_0402_5%  [R_0402]  19.8 100.68 180 bottom
RT23  100K_0402_5%  [R_0402]  27.2 104.2 90 top
RT24  100K_0402_5%  [R_0402]  28.81 110.83 90 top
RT25  100K_0402_5%  [R_0402]  27.08 108.3 90 top
RT26  100K_0402_5%  [R_0402]  23.52 103.96 180 top
RT27  10K_0402_5%  [R_0402]  26.19 108.3 90 top
RT28  100K_0402_5%  [R_0402]  30.38 108.21 90 bottom
RT29  100K_0402_5%  [R_0402]  32.92 101.69 270 top
RT30  1M_0402_5%  [R_0402]  29.7 110.83 90 top
RT31  100K_0402_5%  [R_0402]  20.75 102.47 180 bottom
RT32  100K_0402_5%  [R_0402]  21.49 101.1 90 top
RT33  100K_0402_5%  [R_0402]  27.71 108.18 90 bottom
RT34  3.01K_0402_1%  [R_0402]  30.9 94.87 270 top
RT35  14K_0402_1%  [R_0402]  33.81 101.69 270 top
RT36  100_0402_5%  [R_0402]  23.79 108.19 90 bottom
RT37  100_0402_5%  [R_0402]  39.27 104.02 0 bottom
RT38  14K_0402_1%  [R_0402]  32.03 96.61 270 top
RT39  4.75K_0402_0.5%  [R_0402]  25.86 100.97 0 top
RT40  0_0402_5%  [R0402_0OHM]  21.68 91.31 180 bottom
RT41  499_0402_1%  [R_0402]  25.09 94.79 0 top
RT42  499_0402_1%  [R_0402]  23.77 95.02 270 top
RT48  0_0603_5%  [R_0603]  19.58 109.74 90 top
RT49  0_0603_5%  [R_0603]  20.85 109.74 90 top
RT50  3.3K_0402_5%  [R_0402]  30.14 70.5 180 top
RT51  3.3K_0402_5%  [R_0402]  27.06 69.54 0 top
RT52  3.3K_0402_5%  [R_0402]  27.06 70.5 0 top
RT53  3.3K_0402_5%  [R_0402]  27.06 72.4 0 top
RT54  0_0402_5%  [R0402_0OHM]  30.14 71.51 180 top
RT55  0_0402_5%  [R0402_0OHM]  30.14 72.4 180 top
RT56  0_0402_5%  [R0402_0OHM]  27.06 71.45 0 top
RT57  0_0402_5%  [R0402_0OHM]  27.06 68.59 0 top
RT58  0_0402_5%  [R0402_0OHM]  39.6 79 180 top
RT59  0_0402_5%  [R0402_0OHM]  39 82.56 0 top
RT60  0_0402_5%  [R0402_0OHM]  36.78 81.33 180 bottom
RT63  0_0402_5%  [R0402_0OHM]  32.41 75.84 270 bottom
RT64  0_0402_5%  [R_0402]  35.87 83.23 0 bottom
RT65  0_0402_5%  [R_0402]  35.87 84.12 0 bottom
RT66  3.3K_0402_5%  [R_0402]  37.89 79.25 270 bottom
RT67  3.3K_0402_5%  [R_0402]  37 79.25 270 bottom
RT68  10K_0402_5%  [R_0402]  35.87 82.29 0 bottom
RT69  0_0402_5%  [R_0402]  35.71 76.54 270 bottom
RT70  0_0402_5%  [R0402_0OHM]  34.25 74.93 90 bottom
RT71  1M_0402_5%  [R_0402]  33.74 83.46 270 top
RT72  0_0402_5%  [R0402_0OHM]  30.49 86.48 270 bottom
RT73  0_0402_5%  [R0402_0OHM]  31.29 83.22 0 top
RT74  0_0402_5%  [R_0402]  32.21 84.17 180 top
RT75  0_0402_5%  [R_0402]  34.2 87.89 180 bottom
RT76  10K_0402_1%  [R_0402]  28.42 79.36 180 top
RT81  100K_0402_5%  [R_0402]  32.22 75.14 270 top
RT82  1M_0402_5%  [R_0402]  31.33 75.14 270 top
RT83  0_0402_5%  [R0402_0OHM]  31.32 76.02 0 top
RT84  0_0402_5%  [R_0402]  28.66 75.97 270 top
RT85  0_0402_5%  [R_0402]  28.87 77.54 180 top
RT86  1M_0402_5%  [R_0402]  32.46 85.57 90 bottom
RT87  0_0402_5%  [R0402_0OHM]  24.65 78.05 0 bottom
RT88  0_0402_5%  [R0402_0OHM]  24.65 77.16 0 bottom
RT89  0_0402_5%  [R_0402]  24.65 78.05 0 top
RT90  0_0402_5%  [R_0402]  24.65 77.16 0 top
RT92  0_0402_5%  [R0402_0OHM]  24.65 76.27 0 bottom
RT93  0_0402_5%  [R0402_0OHM]  24.65 75.39 0 bottom
RT95  100K_0402_5%  [R_0402]  28.17 74.94 180 bottom
RT96  100K_0402_5%  [R_0402]  29.03 74.94 0 bottom
RT97  0_0402_5%  [R_0402]  35.87 85.01 0 bottom
RT98  0_0402_5%  [R_0402]  34.2 88.78 180 bottom
RT99  0_0402_5%  [R0402_0OHM]  35.87 85.9 0 bottom
RT100  15K_0402_1%  [R_0402]  30.44 75.97 270 top
RT101  100K_0402_5%  [R_0402]  32.23 80.59 180 top
RT103  0_0402_5%  [R_0402]  27.42 86.62 90 bottom
RT104  0_0402_5%  [R0402_0OHM]  26.06 84.72 270 bottom
RT105  0_0402_5%  [R0402_0OHM]  26.03 87.17 270 bottom
RT106  10K_0402_5%  [R_0402]  29.55 75.97 270 top
RT107  10K_0402_5%  [R_0402]  33.62 80.03 270 top
RT108  0_0402_5%  [R0402_0OHM]  25.83 82.99 180 bottom
RT109  0_0402_5%  [R0402_0OHM]  25.83 82.1 180 bottom
RT110  0_0402_5%  [R_0402]  31.45 85.57 90 bottom
RT111  100K_0402_5%  [R_0402]  21.09 68.15 0 top
RT120  0_0402_5%  [R0402_0OHM]  14.76 107.01 180 top
RT121  0_0402_5%  [R0402_0OHM]  14.76 106.12 180 top
RT122  0_0402_5%  [R0402_0OHM]  13.85 107.01 0 bottom
RT123  0_0402_5%  [R0402_0OHM]  13.85 106.12 0 bottom
RT124  100K_0402_5%  [R_0402]  32.11 108.15 90 top
RT125  100K_0402_5%  [R_0402]  33 108.15 90 top
RT126  100K_0402_5%  [R_0402]  37.79 111.26 0 top
RT127  100K_0402_5%  [R_0402]  36.6 108.55 270 top
RT128  100K_0402_5%  [R_0402]  34.26 99.45 180 top
RT129  100K_0402_5%  [R_0402]  28.09 104.2 90 top
RT336  2.2K_0402_5%  [R_0402]  33.35 98.44 0 top
RT337  2.2K_0402_5%  [R_0402]  28.98 104.2 90 top
RT338  10K_0402_5%  [R_0402]  30.59 110.83 90 top
RT339  0_0402_5%  [R_0402]  32.23 81.48 180 top
RT341  0_0402_5%  [R0402_0OHM]  38.71 110.37 180 top
RT342  0_0402_5%  [R0402_0OHM]  37.5 109.42 180 top
RT371  10K_0402_5%  [R_0402]  34.82 107.5 90 top
RT372  10K_0402_5%  [R_0402]  27.96 108.3 90 top
RT377  43K_0402_1%  [R_0402]  29.3 80.61 270 top
RT391  10K_0402_5%  [R_0402]  135.91 122.89 0 bottom
RT392  0_0402_5%  [R0402_0OHM]  25.56 109.12 270 bottom
RT393  100K_0402_5%  [R_0402]  21.09 69.06 0 top
RT394  0_0402_5%  [R0402_0OHM]  19.92 91.32 180 bottom
RT400  0_0402_5%  [R_0402]  24.68 79.96 0 top
RT401  0_0402_5%  [R_0402]  24.67 80.84 0 top
RT402  0_0402_5%  [R0402_0OHM]  24.68 79.96 0 bottom
RT403  0_0402_5%  [R0402_0OHM]  24.68 80.84 0 bottom
RV1  4.7K_0402_5%  [R_0402]  71.47 126.19 180 top
RV2  4.7K_0402_5%  [R_0402]  72.24 122.31 180 top
RV3  100K_0402_5%  [R_0402]  70.39 122.31 180 top
RV4  270K_0402_5%  [R_0402]  43.08 123.72 270 top
RV5  47K_0402_5%  [R_0402]  42.19 124.59 90 top
RV6  10K_0402_5%  [R_0402]  50.23 120.79 0 top
RV7  100K_0402_5%  [R_0402]  64.21 132.15 0 top
RV8  10K_0402_5%  [R_0402]  61.49 133.31 270 top
RV10  470_0402_1%  [R_0402]  17.72 77.79 180 top
RV11  470_0402_1%  [R_0402]  17.72 78.61 180 top
RV12  470_0402_1%  [R_0402]  17.71 79.4 180 top
RV13  470_0402_1%  [R_0402]  17.71 80.21 180 top
RV14  470_0402_1%  [R_0402]  17.72 82.87 180 top
RV15  470_0402_1%  [R_0402]  17.72 83.76 180 top
RV16  470_0402_1%  [R_0402]  17.72 81.09 180 top
RV17  470_0402_1%  [R_0402]  17.72 81.98 180 top
RV18  10K_0402_5%  [R_0402]  20.53 75.4 270 top
RV19  10K_0402_5%  [R_0402]  26.38 112.14 180 top
RV20  1M_0402_5%  [R_0402]  14.31 98.07 270 top
RV21  20K_0402_5%  [R_0402]  14.31 96.23 270 top
RV22  2.2K_0402_5%  [R_0402]  16.51 89.69 90 top
RV23  2.2K_0402_5%  [R_0402]  16.16 88.77 270 top
RV26  300_0402_5%  [R_0402]  15.99 77.68 270 bottom
RV29  300_0402_5%  [R_0402]  15.99 79.52 270 bottom
RV32  300_0402_5%  [R_0402]  15.99 83.21 270 bottom
RV35  300_0402_5%  [R_0402]  15.99 81.36 270 bottom
RV323  0_0402_5%  [R0402_0OHM]  48.54 119.16 0 top
RV324  0_0402_5%  [R_0402]  48.54 118.27 0 top
RV326  100K_0402_5%  [R_0402]  50.39 119.53 270 top
RV400  0_0402_5%  [R_0402]  50.25 121.54 90 top
RZ8  4.7K_0402_5%  [R_0402]  233.32 55.21 270 top
RZ9  4.7K_0402_5%  [R_0402]  233.32 52.51 90 top
RZ10  100K_0402_5%  [R_0402]  222.53 58.57 270 top
RZ18  4.7K_0402_5%  [R_0402]  209.5 58.49 0 top
RZ19  4.7K_0402_5%  [R_0402]  212.19 58.49 180 top
RZ20  2.2K_0402_5%  [R_0402]  214.07 54.94 0 top
RZ21  2.2K_0402_5%  [R_0402]  216.76 54.94 180 top
RZ22  0_0402_5%  [R_0402]  210.46 57.11 270 top
RZ23  0_0402_5%  [R_0402]  211.34 57.48 0 top
RZ25  150_0402_5%  [R_0402]  285.66 12.58 180 bottom
RZ26  0_0402_5%  [R0402_0OHM]  214.97 55.81 90 top
RZ28  330_0402_5%  [R_0402]  287.55 10.69 270 bottom
RZ29  0_0402_5%  [R0402_0OHM]  215.86 55.81 90 top
RZ32  330_0402_5%  [R_0402]  269.71 83.5 90 top
RZ38  100K_0402_5%  [R_0402]  250.85 120 0 bottom
RZ40  100K_0402_5%  [R_0402]  280.69 86.93 90 top
RZ43  47K_0402_5%  [R_0402]  239.5 111.83 180 top
RZ56  0_0402_5%  [R0402_0OHM]  238.42 67.89 180 top
RZ58  33_0402_5%  [R_0402]  161.52 105.17 180 top
RZ59  33_0402_5%  [R_0402]  160.17 101.09 90 top
RZ60  33_0402_5%  [R_0402]  158.81 102.94 0 bottom
RZ61  0_0402_5%  [R0402_0OHM]  158.08 104.7 90 bottom
RZ62  10K_0402_5%  [R_0402]  155.13 109.3 180 bottom
RZ63  33_0402_5%  [R_0402]  159.99 104.68 90 bottom
RZ64  0_0402_5%  [R0402_0OHM]  160.11 60.86 270 top
RZ65  0_0402_5%  [R_0402]  161 60.86 270 top
RZ69  10K_0402_5%  [R_0402]  161.94 104.68 90 bottom
RZ70  0_0402_5%  [R_0402]  251.75 119.05 180 bottom
RZ71  0_0402_5%  [R_0402]  249.1 120 0 bottom
RZ76  0_0402_5%  [R_0402]  241.01 102.2 180 top
RZ77  0_0402_5%  [R_0402]  241.01 101.31 180 top
RZ78  0_0402_5%  [R_0402]  237.5 67 0 top
RZ79  0_0402_5%  [R_0402]  237.5 66.11 0 top
RZ80  0_0402_5%  [R_0402]  237.5 65.23 0 top
RZ81  0_0402_5%  [R_0402]  237.5 64.34 0 top
RZ85  0_0402_5%  [R0402_0OHM]  223.53 52.84 0 top
RZ87  0_0402_5%  [R0402_0OHM]  221.64 58.57 270 top
RZ89  0_0402_5%  [R0402_0OHM]  160.58 115.73 0 bottom
RZ112  0_0402_5%  [R0402_0OHM]  154.21 110.28 0 bottom
RZ114  0_0402_5%  [R_0402]  223.79 58.57 270 top
RZ116  10K_0402_5%  [R_0402]  214.08 55.81 90 top
RZ117  10K_0402_5%  [R_0402]  216.75 55.81 90 top
RZ119  0_0402_5%  [R_0402]  134.64 68.39 90 top
RZ120  0_0402_5%  [R0402_0OHM]  140.18 66.3 180 top
RZ128  0_0201_5%  [R_0201]  233.51 84.59 270 bottom
RZ129  0_0201_5%  [R_0201]  234.17 84.59 270 bottom
RZ130  0_0201_5%  [R_0201]  234.83 84.59 270 bottom
RZ132  0_0402_5%  [R_0402]  237.79 97.22 0 top
RZ151  0_0603_5%  [R_0603]  120.86 123.07 0 top
RZ320  0_0402_5%  [R_0402]  124.56 130.82 180 bottom
RZ326  0_0402_5%  [R_0402]  231.05 106.06 180 top
RZ334  51_0402_5%  [R_0402]  277.65 58.51 270 bottom
RZ335  15K_0402_5%  [R_0402]  277.65 55.76 90 bottom
RZ345  0_0402_5%  [R0402_0OHM]  203.99 52.28 270 top
RZ346  0_0402_5%  [R0402_0OHM]  213.19 55.81 90 top
RZ347  0_0402_5%  [R0402_0OHM]  216.76 57.61 180 top
RZ361  100_0402_5%  [R_0402]  241.96 93 180 top
RZ362  10K_0402_5%  [R_0402]  154.21 111.1 0 bottom
RZ363  0_0402_5%  [R_0402]  159.55 115.16 270 bottom
RZ364  100_0402_5%  [R_0402]  232.94 59.07 180 top
RZ365  0_0402_5%  [R0402_0OHM]  162.79 104.61 0 bottom
RZ366  0_0402_5%  [R_0402]  162.81 105.57 0 bottom
RZ367  0_0402_5%  [R_0402]  162.46 116.6 270 bottom
RZ368  0_0402_5%  [R0402_0OHM]  160.68 116.72 0 bottom
RZ369  0_0402_5%  [R_0402]  155.5 116.32 0 bottom
RZ370  100_0603_5%  [R_0603]  241.5 118.88 0 bottom
RZ380  0_0402_5%  [R_0402]  57.69 122.06 180 top
RZ518  10K_0402_5%  [R_0402]  246.92 120 0 bottom
SHDCAN  -  [SION_SUS304_1P-T]  20.05 84.59 180 bottom
SW1  SS3-CMFTQR9_3P  [SW_SS3-CMFTQR9_3P]  228.24 82.83 65 bottom
SW3  SKRBACE010_4P  [SW_SKRBAAE010_4P]  295.67 126.44 180 top
T1  PAD~D  [TPC12]  105.42 109.08 0 top
T2  PAD~D  [TPC12]  105.1 110.35 0 top
T3  PAD~D  [TPC12]  97.88 84.62 0 top
T4  PAD~D  [TPC12]  97.94 85.79 180 bottom
T9  PAD~D  [TPC12]  83.92 120.82 180 bottom
T10  PAD~D  [TPC12]  101.65 115.53 180 bottom
T11  PAD~D  [TPC12]  100.61 116.28 180 bottom
T12  PAD~D  [TPC12]  84.73 86.5 180 bottom
T13  PAD~D  [TPC12]  87.27 86.5 180 bottom
T14  PAD~D  [TPC12]  125.18 98.88 0 top
T15  PAD~D  [TPC12]  126.69 98.49 0 top
T16  PAD~D  [TPC12]  86 86.5 180 bottom
T17  PAD~D  [TPC12]  84.73 87.77 180 bottom
T50  PAD~D  [TPC12]  118.45 51.45 180 bottom
T51  PAD~D  [TPC12]  119.85 60.15 0 top
T88  PAD~D  [TPC12]  242.42 132.13 0 top
T89  PAD~D  [TPC12]  243.47 130.81 0 top
T113  PAD~D  [TPC12]  87.27 87.77 180 bottom
T114  PAD~D  [TPC12]  86 87.77 180 bottom
T115  PAD~D  [TPC12]  125.08 95.43 0 top
T120  PAD~D  [TPC12]  125.78 106.26 0 top
T122  PAD~D  [TPC12]  114.18 108.27 0 top
T123  PAD~D  [TPC12]  114.34 97.86 0 top
T126  PAD~D  [TPC12]  136.88 89.75 180 bottom
T127  PAD~D  [TPC12]  135.63 90.16 180 bottom
T130  PAD~D  [TPC12]  135.48 88.66 180 bottom
T132  PAD~D  [TPC12]  93.6 91.98 0 top
T141  PAD~D  [TPC12]  248.89 81.86 0 top
T142  PAD~D  [TPC12]  258.38 93.85 0 top
T143  PAD~D  [TPC12]  260.63 85.46 0 top
T144  PAD~D  [TPC12]  256.73 81.92 0 top
T147  PAD~D  [TPC12]  259.19 83.91 0 top
T219  PAD~D  [TPC12]  28.68 74.1 180 top
T220  PAD~D  [TPC12]  27.02 77.56 90 top
T225  PAD~D  [TPC12]  230.94 95.26 0 top
T226  PAD~D  [TPC12]  94.46 90.97 0 top
T258  PAD~D  [TPC12]  134.64 87.58 180 bottom
T262  PAD~D  [TPC12]  253.87 79.86 0 top
T264  PAD~D  [TPC12]  250.52 95.39 0 top
T268  PAD~D  [TPC12]  136.07 87.49 180 bottom
T269  PAD~D  [TPC12]  136.88 115.3 180 bottom
T283  PAD~D  [TPC12]  162.84 109.1 180 bottom
TL1  MHPC_NS692417  [MHPC_NS692417_24P]  258.72 128.94 0 bottom
UA1  -  [ALC3246-CG_MQFN48_6X6]  259.53 63.39 270 top
UC1  KBL-RU42_BGA1356  [KBL-RU42_BGA_1356P-T]  132.41 113.31 0 bottom
UC5  W25Q128JVSIQ_SO8  [W25Q128FVSIQ_SO8]  160.68 95.32 270 bottom
UC6  W25Q128JVSIQ_SO8  [W25Q128FVSIQ_SO8-NPM]  160.68 101.23 270 bottom
UC7  TC7SH08FU_SSOP5~D  [TC7SH08FU_SSOP5]  156.68 119.79 270 bottom
UC8  74CBTLV3126BQ_DHVQFN14_2P5X3  [74CBTLV3126BQ_DHVQFN14_2P5X3-S]  82.78 122.3 180 bottom
UC12  -  [74AHC1G09GW_TSSOP5]  151.16 116.61 270 bottom
UD1  74AUP1G07SE-7_SOT353_5P  [74AUP1G07GW_TSSOP5]  77.47 80.45 180 top
UE1  MEC5105_WFBGA169_11X11  [MEC5105_WFBGA_169P]  246.68 83.86 90 top
UE3  TC7SH08FU_SSOP5~D  [TC7SH08FU_SSOP5]  266.6 98.9 270 top
UE4  -  [74AUP1G07GW_TSSOP5]  269.88 96.78 0 top
UE5  TC7SH08FU_SSOP5~D  [TC7SH08FU_SSOP5]  263.23 98.96 270 top
UE6  -  [74AUP1G07GW_TSSOP5]  266.65 80.73 270 top
UI1  -  [SY6288D20AAC_SOT23-5]  20.02 55.47 0 bottom
UI3  -  [SLGC55544CVTR_TQFN16_3X3]  277.51 77.32 180 top
UL1  WGI219LM-QREF- A0_QFN48_6X6~D  [WGI217LM-QPN9-A2_QFN48_6X6-S]  244.08 122.96 0 top
UL2  TC7SH08FU_SSOP5~D  [TC7SH08FU_SSOP5]  254.97 132.74 270 bottom
UR1  RTS5242-GR_QFN32_4X4  [RTS5242-GR_QFN32_4X4-S]  273.22 66.27 0 top
UT1  ALPINE-RIDGE_BGA337  [ALPINE-RIDGE_BGA_337P]  22.65 104.38 270 bottom
UT2  -  [W25Q80DVSSIG_SO8]  38.16 89.52 0 bottom
UT5  TPS65982DC_BGA96  [TPS65982_BGA_96P]  34.02 78.47 90 bottom
UT6  GD25Q80CSIGR_SO8  [W25Q80DVSSIG_SO8]  25.04 68.59 90 bottom
UT7  AP2112K-3.3TRG1_SOT23-5  [AP2112K-3P3TRG1_SOT23-5]  19.97 67.56 0 bottom
UT8  AP2204R-5.0TRG1_SOT89-3  [AP2204R-5P0TRG1_SOT89-3]  16.91 74.98 270 bottom
UV2  -  [AP2330W-7_SC59-3]  12.79 98.94 180 bottom
UV24  -  [G524B1T11U_SOT23-5]  66.8 125.27 180 top
UZ2  EM5209VF_SON14_2X3  [TPS22966DPUR_SON14_2X3]  252.32 110 90 top
UZ3  EM5209VF_SON14_2X3  [TPS22966DPUR_SON14_2X3]  158.59 59.14 90 top
UZ4  EM5209VF_SON14_2X3  [TPS22966DPUR_SON14_2X3]  279.19 89.74 90 top
UZ5  EM5209VF_SON14_2X3  [TPS22966DPUR_SON14_2X3]  245.38 65.03 270 top
UZ6  TC7SH08FU_SSOP5~D  [TC7SH08FU_SSOP5]  203.1 59.72 270 top
UZ8  -  [AOZ1336_DFN8_2X2]  206.38 52.39 270 top
UZ10  TC7SH08FU_SSOP5~D  [TC7SH08FU_SSOP5]  268.56 84.83 90 top
UZ12  NPCT750JAAYX_QFN32_5X5  [NPCT650JB2YX_QFN32_5X5]  157.33 112.52 270 bottom
UZ19  -  [TPS22961DNYR_WSON8]  121.9 130.69 180 top
UZ21  -  [TPS22961DNYR_WSON8]  126.29 130.58 180 top
UZ26  -  [TPS22961DNYR_WSON8]  135.89 66.61 0 top
UZ34  TC7SH08FU_SSOP5~D  [TC7SH08FU_SSOP5]  140.44 69.6 180 top
UZ35  TC7SH08FU_SSOP5~D  [TC7SH08FU_SSOP5]  125.43 133.12 270 bottom
YC1  24MHZ_12PF_X3G024000DC1H  [Y_X3G024000DC1H_4P]  112.84 122.04 0 bottom
YC2  32.768KHZ_12.5PF_9H03200042  [Y_9H03200042_2P]  134.81 80.15 180 top
YC3  24MHZ_12PF_X3G024000DC1H  [Y_X3G024000DC1H_4P]  131.38 122.65 0 bottom
YE1  32.768KHZ_9PF_X1A000141000200  [Y_X1A000141000200_2P]  242.02 82.2 90 top
YL1  25MHZ_18PF_7V25000034  [Y_7V25000034_4P]  248.9 118.13 180 top
YT1  25MHZ 20PF FL2500123Z  [Y_7V25000034_4P]  18.97 89.18 0 bottom

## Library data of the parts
CA1-CA6 CA12 CA13 CA19 CA22-CA24 CA27 CA28 CA33 CA35 CA41 CA54 CA62-CA69 CA72 CA78 CC7 CC8 CC21-CC27 CC32 CC33 CC176-CC179 CC195 CC199 CC202-CC209 CC211-CC213 CC215-CC218 CC222 CC224 CC250-CC253 CC264-CC266 CC269 CC288 CC297 CC300-CC308 CC310 CC312 CC316 CC318-CC326 CC331-CC335 CC340 CD9-CD16 CD18 CD19 CD23-CD27 CD29 CD31 CE3 CE4 CE8 CE10 CE12 CE14 CE24 CE26-CE31 CE35-CE40 CE46 CE47 CE52-CE54 CE57 CE59-CE66 CI4 CI5 CI13 CI16 CI29-CI31 CI43-CI46 CL1 CL2 CL5 CL6 CL13 CL14 CL18 CL29 CL30 CN60 CN65-CN72 CR1 CR4 CR11-CR15 CR21 CR22 CR25-CR28 CT20 CT21 CT44-CT47 CT59 CT60 CT67 CT70-CT74 CT83 CT85-CT87 CT89 CT90 CT92 CT93 CT189 CV1-CV6 CV13 CV14 CV17-CV25 CV31-CV38 CV635 CZ3 CZ12 CZ13 CZ17-CZ19 CZ21 CZ23-CZ25 CZ28 CZ29 CZ33-CZ41 CZ56-CZ63 CZ69 CZ71-CZ73 CZ75-CZ78 CZ80 CZ81 CZ83 CZ100 CZ102 CZ104 CZ105 CZ109 CZ110 CZ113 CZ114 CZ117 CZ118 CZ121 CZ124 CZ126 CZ127 CZ197 CZ198 CZ200 PC1 PC2 PC9 PC10 PC12 PC100 PC103 PC113 PC115 PC116 PC127 PC133-PC143 PC202 PC203 PC206-PC208 PC216-PC218 PC221 PC222 PC224 PC301 PC303 PC307 PC314-PC316 PC401 PC402 PC408-PC411 PC417-PC420 PC503 PC505 PC506 PC513 PC515 PC601 PC602 PC605 PC613 PC614 PC616-PC621 PC624-PC633 PC635-PC647 PC649-PC654 PC659-PC661 PC668 PC669 PC676 PC677 PC679-PC681 PC685 PC689-PC692 PC695-PC697 PC700-PC703 PC902 PC903 PC925-PC929 PC932 PC933 PC937-PC939 PC942-PC947 PC949 PC950 PC955-PC962 PC1201 PC1203-PC1208 PC1210-PC1214 PC1216 PC1217 = C_0402
CA7 CA8 CA10 CA45 CA47 CA55 CA57 CA60 CC9 CC10 CC28-CC30 CC214 CC223 CC270 CC281 CC313 CC314 CD28 CD32 CE11 CE13 CE15 CE18-CE23 CE25 CI3 CI7 CI17 CI19 CL3 CL7-CL11 CL15-CL17 CL19-CL21 CN61 CN62 CR2 CR3 CR6 CR7 CR17 CR19 CT1-CT19 CT25-CT43 CT48-CT54 CT61-CT64 CT80 CT81 CT88 CT95-CT102 CT123-CT130 CT168-CT177 CT201-CT204 CV12 CV39 CV40 CZ1 CZ2 CZ30 CZ31 CZ50 CZ51 CZ53 CZ54 CZ64 CZ66-CZ68 CZ82 CZ90-CZ93 CZ101 CZ103 CZ106 CZ111 CZ112 CZ115 CZ116 CZ119 CZ120 CZ122 CZ125 CZ128 PC1030-PC1053 PC1055 PC1056 PC1083-PC1099 PC1147-PC1153 PC1328-PC1334 = C_0201
CA9 CA25 CA29 CA31 CA43 CA44 CA46 CA48 CA49 CA51-CA53 CA56 CA58 CA59 CA61 CC279 CC280 CC294-CC296 CC341 CD1-CD8 CD20-CD22 CE16 CE17 CE32 CI6 CI33 CI34 CL4 CL12 CN63 CN64 CR5 CR18 CR20 CT55-CT57 CT82 CT84 CT91 CT94 CV11 CV15 CV16 CV41 CZ20 CZ27 CZ32 CZ52 CZ55 PC3-PC7 PC11 PC102 PC104 PC105 PC111 PC112 PC114 PC119 PC125 PC126 PC128 PC204 PC205 PC209-PC214 PC219 PC223 PC302 PC304-PC306 PC308-PC313 PC403 PC404 PC406 PC407 PC412 PC413 PC415 PC424-PC428 PC501 PC504 PC514 PC516 PC530 PC531 PC603 PC604 PC608 PC611 PC612 PC622 PC655-PC658 PC662-PC665 PC670-PC675 PC678 PC682-PC684 PC930 PC931 PC934 PC940 PC941 PC1001-PC1029 PC1057-PC1061 PC1064-PC1082 PC1129-PC1146 PC1202 PC1322-PC1327 = C_0603
CC210 CC219-CC221 CC225 CC226 CL28 CT68 CT69 CT75-CT78 PC8 PC106-PC110 PC117 PC118 PC120-PC124 PC129 PC130 PC200 PC201 PC904-PC906 PC911 PC913-PC916 PC935 PC936 PC951 PC952 = C_0805
CD17 PC1062 PC1063 = C_D3
CI1 CI14 = C_1206
CI32 CZ26 PC909 PC921 = C_B2
CL22 = C_1808
CLIP1 = CLIP_14P0X2P6
CLIP2 = CLIP_7P7X4P2
CMOS1 = SHORTPADS-NPM: User Part Number: PART#
DA1-DA3 DA6 DA7 = L03ESDL5V0CC3-2_SOT23-3
DA8 DC1 DC2 DE2 DZ1 DZ2 DZ5-DZ8 = AZ5125-01HPR7G_SOD523-2
DE1 = BZV55-B5V1_SOD80C2
DI1 DI4 DT39 DT40 = L05ESDL5V0NA-4_SLP2510P8-10-9
DI2 DI5 DV4 = AZC199-02SPR7G_SOT23-3
DT1-DT3 = 1N4148WS-7-F_SOD323-2
DT4 = L30ESD24VC3-2_SOT23-3
DT5 DT6 DT9 DT10 DT13 DT14 DT17 DT18 DV7 DV8 = ESD8011MUT5G_X3DFN2-2-S
DV1-DV3 DZ9 PD905 PD1801 = BAT54CW_SOT323-3
FD1-FD4 = FIDUCIAL_C40M80
H1-H4 = H_3P4
H5 H6 = H_1P0N
H7 H8 H25 H26 = H_3P2
H9 H14-H16 H18 H23 H24 H29 H33 H38 = H_2P6-G
H10 = H_3P8-G
H12 H21 H22 H27 H28 = H_3P5-G
H20 H37 = H_3P1-G
H30 = H_2P3X2P7N
H39 = H_2P3N
JAPS1 = CVILU_CF4218FH0R0-05-NH_18P-T
JDB1 = ACES_50506-00641-P01_6P
JDEG1 = HB_A531015-SCHR21_10P
JDIMM1 = LCN_DAN05-Q0406-0103_260P
JEDP1 = ACES_50398-04041-001_40P
JESPI = ACES_50506-01041-P01_10P
JFAN1 = ACES_50271-0040N-001_4P
JHDMI1 = ACON_HMRBL-A41L0F_19P-T
JHP1 = SINGA_2SJ3095-085111F_6P
JIR1 = E-T_4251K-F06N-40L_6P
JKBTP1 = CVILU_CF5020FD0RK-05-NH_20P-T
JLED1 = ACES_50209-0060N-P01_6P
JLOM1 = SANTA_130470-19_13P-T
JNGFF1 = LCN_DAN05-67306-0100_75P
JNGFF2 = BELLW_80149-3221_67P
JNGFF3 = LOTES_APCI0170-P001A_75P
JRTC1 = ACES_50271-0020N-001_2P
JSD1 = T-SOL_158-1240902600_23P-T
JSIM1 = JAE_SF51S006V4DR1000Q_8P
JSPI1 = CVILU_CF5020FD0R0-05-NH_20P
JSPK1 = ACES_50278-0040N-001_4P
JTAG1 = SHORTPADS: User Part Number: PART#
JUART1 = CVILU_CI1804M1VRA-NH_4P
JUSB1 JUSB2 = ACON_TCRA2-9U1U93_9P-T
JUSBC1 = JAE_DX07B024XJ1R1300_24P
JUSH1 = CVILU_CF5026FD0RK-05-NH_26P-T
JXDP1 = JXT_FP270H-061G1AM_61P
LA5 LA12 LA14 = MURAT_BLM15PX600SN1D_2P
LA6-LA11 = MURAT_BLM15PX330SN1D_2P
LA13 PL1201 PL1202 = TAI-T_HCB2012KF-121T50_2P
LC1 LC2 = MURAT_BLM15GA750SN1D_2P
LED3 = LED_LTW-C193DC-C_2P
LI3 LI7 LV27 LZ1 = PANAS_EXC24CQ900U_4P
LI8 LI9 = INPAQ_MCM1012B900F06BP_4P
LI16 LI17 = INPAQ_HCM1012GH900BP_4P
LL1 = TAIYO_BRC2012T4R7MD_2P
LT1 = MAG_MND-04ABIR60M-XGL_2P
LT2 = MURAT_LQM18NN1R0K00D_2P
LV1 = MURAT_BLM15PX221SN1D_2P
LV3 LV6 LV9 LV12 = TAIYO_MCF12102G900-T_4P-NPM
LV31-LV38 = MURAT_LQG15HN12NJ02D_2P
PBATT1 = DEREN_40-42251-01001RHF_10P-T
PC606 PC607 = C_D
PC1127 PC1128 = C_D2
PC1321 = C_D7
PD1 PD2 = TVNST52302AB0_SOT523-3
PD3 = DB3J315E0L_SMINI3-F2-B3
PD4 = PESD5V0U2BT_SOT23-3
PD5 PD1202 = PDS5100H-13_POWERDI5-3
PD6 = DFLS160-7_POWERDI123-2
PD901 PD904 PD1205 = SDMK0340L-7-F_SOD323-2
PD903 = RB520SM-30T2R_EMD2-2
PD906 = SMF22A-SOD123FL-2-S
